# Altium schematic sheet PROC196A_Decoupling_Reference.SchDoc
size 431 x 279 mm; Date: Not shown in title block; ApprovedBy: Not shown in title block; CheckedBy: Not shown in title block; Author: Not shown in title block; CompanyName: Not shown in title block; Engineer: Not shown in title block; Organization: Not shown in title block; Address1: Not shown in title block; Address2: Not shown in title block; Address3: Not shown in title block; Address4: Not shown in title block; DocumentNumber: 4; Revision: Use project parameter SCH_Rev; SheetNumber: 4; SheetTotal: 25; PageSetup: Record=PageOptions¦CenterHorizontal=True¦CenterVertical=True¦PrintScale=1.00¦XCorrection=1.00¦YCorrection=1.00¦PrintKind=0¦BorderSize=5000000¦LeftOffset=0¦BottomOffset=0¦Orientation=2¦PaperLength=1000¦PaperWidth=1000¦Scale=100¦PaperSource=15¦PrintQuality=600¦MediaType=1¦DitherType=10¦PaperKind=Letter¦PrintScaleMode=1
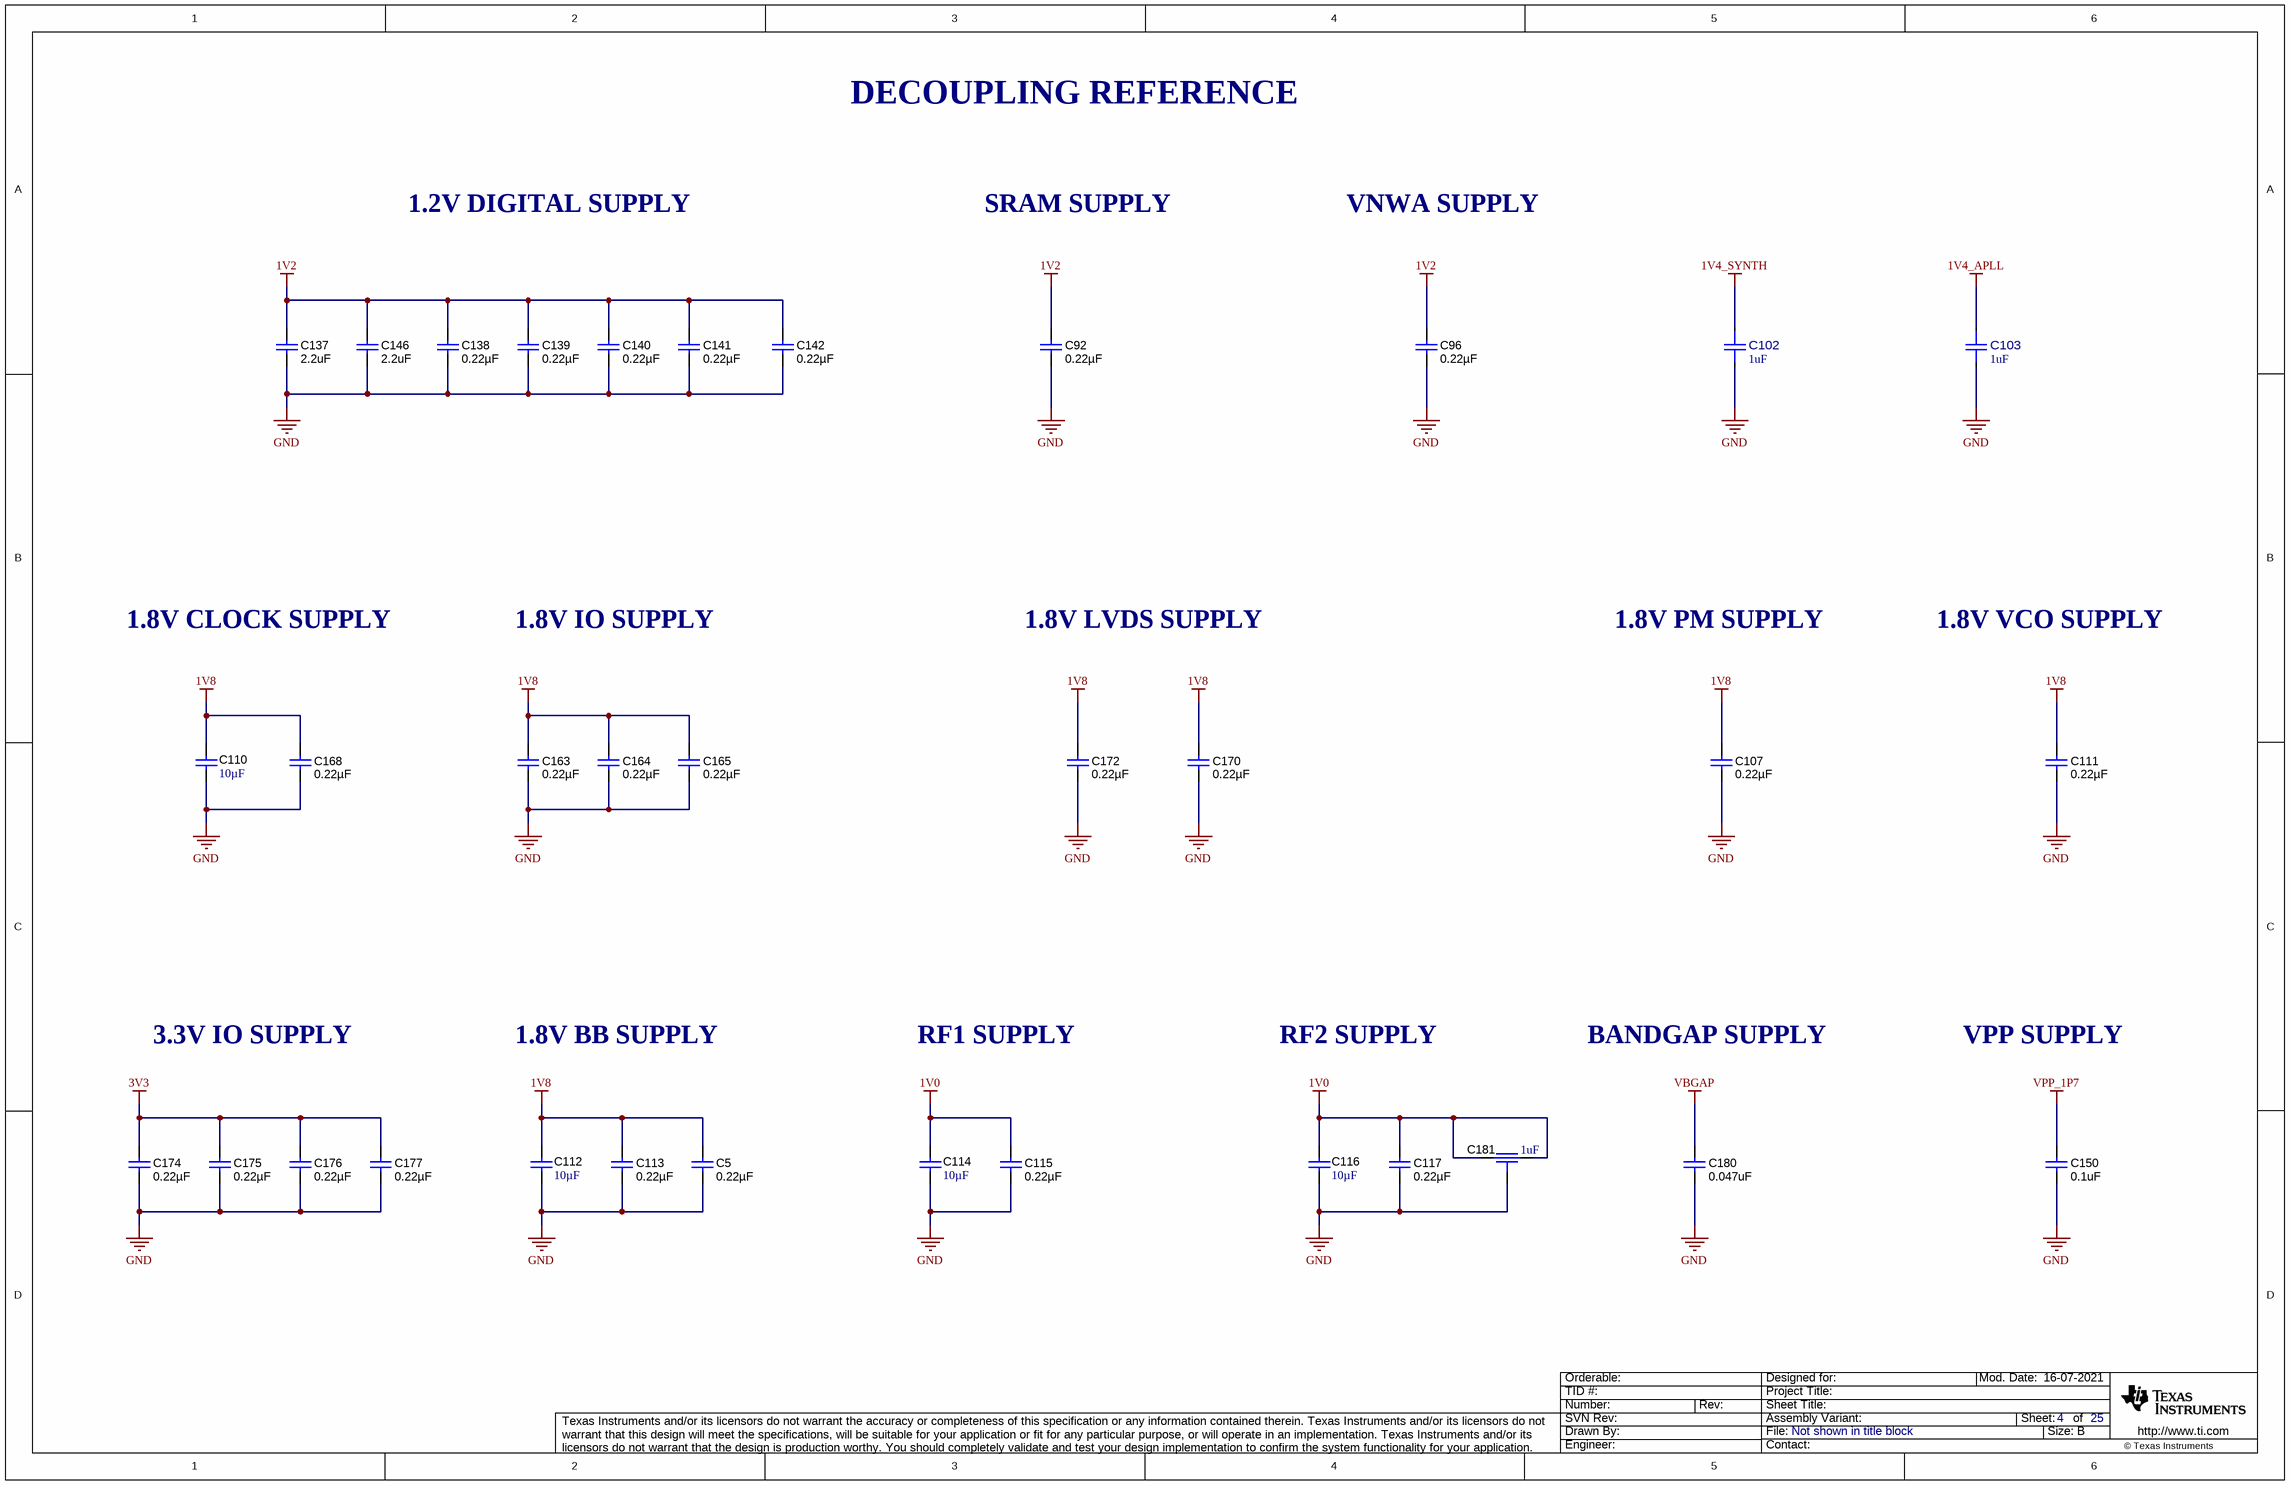
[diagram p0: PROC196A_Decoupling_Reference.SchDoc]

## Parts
C5  ValueDisplayed: 0.22µF  [0402L]  (hidden comment: GCM155R71C224KE02D)
C92  ValueDisplayed: 0.22µF  [0402L]  (hidden comment: GCM155R71C224KE02D)
C96  ValueDisplayed: 0.22µF  [0402L]  (hidden comment: GCM155R71C224KE02D)
C102  ValueDisplayed: 1uF  [FP-GRT155R70J105KE01D_0402-MFG]  (hidden comment: GRT155R70J105KE01D)
C103  ValueDisplayed: 1uF  [FP-GRT155R70J105KE01D_0402-MFG]  (hidden comment: GRT155R70J105KE01D)
C107  ValueDisplayed: 0.22µF  [0402L]  (hidden comment: GCM155R71C224KE02D)
C110  Cap_F: 10µF  [0805L]  (hidden comment: GCM21BR71A106KE22L)
C111  ValueDisplayed: 0.22µF  [0402L]  (hidden comment: GCM155R71C224KE02D)
C112  Cap_F: 10µF  [0805L]  (hidden comment: GCM21BR71A106KE22L)
C113  ValueDisplayed: 0.22µF  [0402L]  (hidden comment: GCM155R71C224KE02D)
C114  Cap_F: 10µF  [0805L]  (hidden comment: GCM21BR71A106KE22L)
C115  ValueDisplayed: 0.22µF  [0402L]  (hidden comment: GCM155R71C224KE02D)
C116  Cap_F: 10µF  [0805L]  (hidden comment: GCM21BR71A106KE22L)
C117  ValueDisplayed: 0.22µF  [0402L]  (hidden comment: GCM155R71C224KE02D)
C137  ValueDisplayed: 2.2uF  [0603L]  (hidden comment: GCM188R70J225KE22D)
C138  ValueDisplayed: 0.22µF  [0402L]  (hidden comment: GCM155R71C224KE02D)
C139  ValueDisplayed: 0.22µF  [0402L]  (hidden comment: GCM155R71C224KE02D)
C140  ValueDisplayed: 0.22µF  [0402L]  (hidden comment: GCM155R71C224KE02D)
C141  ValueDisplayed: 0.22µF  [0402L]  (hidden comment: GCM155R71C224KE02D)
C142  ValueDisplayed: 0.22µF  [0402L]  (hidden comment: GCM155R71C224KE02D)
C146  ValueDisplayed: 2.2uF  [0603L]  (hidden comment: GCM188R70J225KE22D)
C150  ValueDisplayed: 0.1uF  [0402L]  (hidden comment: GCM155R71C104KA55D)
C163  ValueDisplayed: 0.22µF  [0402L]  (hidden comment: GCM155R71C224KE02D)
C164  ValueDisplayed: 0.22µF  [0402L]  (hidden comment: GCM155R71C224KE02D)
C165  ValueDisplayed: 0.22µF  [0402L]  (hidden comment: GCM155R71C224KE02D)
C168  ValueDisplayed: 0.22µF  [0402L]  (hidden comment: GCM155R71C224KE02D)
C170  ValueDisplayed: 0.22µF  [0402L]  (hidden comment: GCM155R71C224KE02D)
C172  ValueDisplayed: 0.22µF  [0402L]  (hidden comment: GCM155R71C224KE02D)
C174  ValueDisplayed: 0.22µF  [0402L]  (hidden comment: GCM155R71C224KE02D)
C175  ValueDisplayed: 0.22µF  [0402L]  (hidden comment: GCM155R71C224KE02D)
C176  ValueDisplayed: 0.22µF  [0402L]  (hidden comment: GCM155R71C224KE02D)
C177  ValueDisplayed: 0.22µF  [0402L]  (hidden comment: GCM155R71C224KE02D)
C180  ValueDisplayed: 0.047uF  [0402L]  (hidden comment: CGA2B3X7R1H473K050BB)
C181  ValueDisplayed: 1uF  [FP-NFM18HC105C1C3D_0603-MFG]  (hidden comment: NFM18HC105C1C3D)

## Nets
1V0: C114.1 C115.2 C116.1 C117.2 C181.1 C181.3
1V2: C92.2 C96.2 C137.2 C138.2 C139.2 C140.2 C141.2 C142.2 C146.2
1V4_APLL: C103.1
1V4_SYNTH: C102.1
1V8: C5.2 C107.2 C110.1 C111.2 C112.1 C113.2 C163.2 C164.2 C165.2 C168.2 C170.2 C172.2
3V3: C174.2 C175.2 C176.2 C177.2
GND: C5.1 C92.1 C96.1 C102.2 C103.2 C107.1 C110.2 C111.1 C112.2 C113.1 C114.2 C115.1 C116.2 C117.1 C137.1 C138.1 C139.1 C140.1 C141.1 C142.1 C146.1 C150.1 C163.1 C164.1 C165.1 C168.1 C170.1 C172.1 C174.1 C175.1 C176.1 C177.1 C180.2 C181.2
VBGAP: C180.1
VPP_1P7: C150.2

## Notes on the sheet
- DECOUPLING REFERENCE
- 1.2V DIGITAL SUPPLY
- SRAM SUPPLY
- VNWA SUPPLY
- 1.8V CLOCK SUPPLY
- 1.8V IO SUPPLY
- 1.8V LVDS SUPPLY
- 1.8V PM SUPPLY
- 1.8V VCO SUPPLY
- 3.3V IO SUPPLY
- 1.8V BB SUPPLY
- RF1 SUPPLY
- RF2 SUPPLY
- BANDGAP SUPPLY
- VPP SUPPLY

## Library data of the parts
C5 C92 C96 C107 C111 C113 C115 C117 C138-C142 C163-C165 C168 C170 C172 C174-C177 = CMP-0078265-1: CAP, CERM, 0.22 µF, 16 V,+/- 10%, X7R, AEC-Q200 Grade 1, 0402; Manufacturer: MuRata; TaMin_C: -55°C; Polarized: N; SizeAreaWB_mm2: 3; U/M: EA; Value: 0.22uF; TaMax_C: 125°C; SizeZ_mm: 0.6; SizeX_mm: 1; SizeY_mm: 0.5; Cap_Case: 0402; Value2: 16V; CompType: Capacitor; AEC Qualified: Y; Cap_F: 220nF; AEC Category: Q200
C102 C103 = CMP-0088425-1: 1µF ±10% 6.3V Ceramic Capacitor X7R 0402 (1005 Metric); Manufacturer: Murata; AEC Grade: Grade 1; SizeZ_mm: 0.55mm; AEC Qualified: Yes; TempCo: 15%
C110 C112 C114 C116 = CMP-0008017-2: CAP, CERM, 10 uF, 10 V, +/- 10%, X7R, 0805; Manufacturer: MuRata; TaMin_C: -55°C; Polarized: N; SizeAreaWB_mm2: 6.75; Value1: Unknown; U/M: EA; Value: 10uF; TaMax_C: 125°C; SizeZ_mm: 1.45; SizeX_mm: 2; SizeY_mm: 1.25; Cap_Case: 0805; Value2: 10V; SizeArea_mm2: 2.5; AEC Category: Q200
C137 C146 = CMP-0007134-5: CAP, CERM, 2.2 uF, 6.3 V, +/- 10%, X7R, AEC-Q200 Grade 1, 0603; Manufacturer: MuRata; TaMin_C: -55°C; Polarized: N; SizeAreaWB_mm2: 4.68; Value1: Unknown; U/M: EA; Value: 2.2uF; TaMax_C: 125°C; SizeZ_mm: 1; SizeX_mm: 1.6; SizeY_mm: 0.8; Cap_Case: 0603; Value2: 6.3V; SizeArea_mm2: 1.28; AEC Qualified: Y; Cap_F: 2.2µF; AEC Category: Q200
C150 = CMP-0006351-2: CAP, CERM, 0.1 uF, 16 V, +/- 10%, X7R, 0402; Manufacturer: MuRata; TaMin_C: -55°C; Polarized: N; SizeAreaWB_mm2: 3; Value1: Unknown; U/M: EA; Value: 0.1uF; TaMax_C: 125°C; SizeZ_mm: 0.6; SizeX_mm: 1; SizeY_mm: 0.5; Cap_Case: 0402; Value2: 16V; Cap_F: 100nF; AEC Category: Q200
C180 = CMP-0006330-2: CAP, CERM, 0.047 uF, 50 V, +/- 10%, X7R, AEC-Q200 Grade 1, 0402; Manufacturer: TDK; TaMin_C: -55°C; ESR_ohm: 0.06407; Polarized: N; SizeAreaWB_mm2: 3; Value1: 0.06407 ohm; U/M: EA; TaMax_C: 125°C; SizeZ_mm: 0.6; SizeX_mm: 1; SizeY_mm: 0.5; Cap_Case: 0402; Value2: 50V; AEC Qualified: Y; Cap_F: 47nF; IRMS_A: 646.122mA; AEC Category: Q200
C181 = CMP-0088247-2: 3 Terminals Low ESL Chip Multilayer Ceramic Capacitors for Automotive; Manufacturer: Murata; VDC_V: 16V; SizeZ_mm: 0.7mm; Tolerance_%: 20%; AEC Grade: Grade 1; Cap_F: 1µF; AEC Qualified: Yes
